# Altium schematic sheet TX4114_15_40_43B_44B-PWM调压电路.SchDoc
size A4
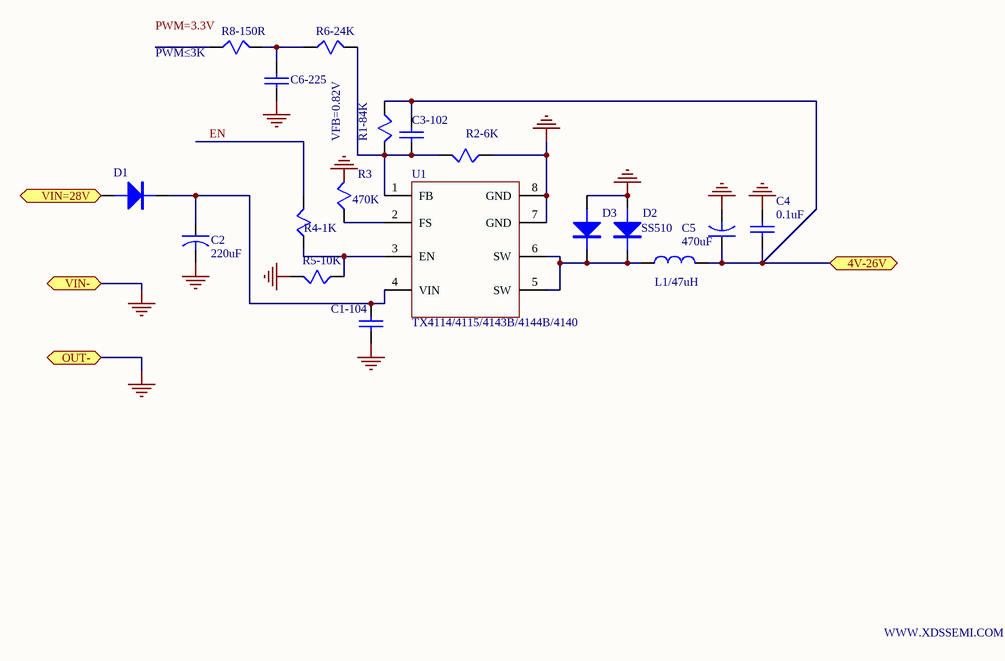
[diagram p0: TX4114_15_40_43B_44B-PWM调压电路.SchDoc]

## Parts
C1-104  (no value)  [0805R]
C2  220uF  [c8*12]
C3-102  (no value)  [0805R]
C4  0.1uF  [1206R]
C5  470uF  [C8*12]
C6-225  (no value)  [0805R]
D1  DIODE  [SMB]  (value not drawn)
D2  SS510  [SMB]
D3  (no value)  [SMB]
L1/47uH  (no value)  [CDRH127]
R1-84K  (no value)  [0805R]
R2-6K  (no value)  [0805R]
R3  470K  [0805R]
R4-1K  (no value)  [0805R]
R5-10K  (no value)  [0805R]
R6-24K  (no value)  [0805R]
R8-150R  (no value)  [0805R]
U1  TX4114/4115/4143B/4144B/4140

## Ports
4V-26V, OUT-, VIN-, VIN=28V

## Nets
GND: C1-104.2 C2.2 C4.1 C5.2 C6-225.1 D2.1(A) D3.1(A) R2-6K.1 R3.2 R5-10K.2 U1.7(GND) U1.8(GND) ; port VIN-, port OUT-
4V-26V: C3-102.2 C4.2 C5.1 L1/47uH.2 R1-84K.1 ; port 4V-26V
EN: R4-1K.2
VIN=28V: D1.1(A) ; port VIN=28V
NetC1-104_1: C1-104.1 C2.1 D1.2(K) U1.4(VIN)
NetC3-102_1: C3-102.1 R1-84K.2 R2-6K.2 R6-24K.2 U1.1(FB)
NetC6-225_2: C6-225.2 R6-24K.1 R8-150R.2
NetD2_2: D2.2(K) D3.2(K) L1/47uH.1 U1.5(SW) U1.6(SW)
NetR3_1: R3.1 U1.2(FS)
NetR4-1K_1: R4-1K.1 R5-10K.1 U1.3(EN)

Not connected (* = marked no-connect by the designer): R8-150R 1

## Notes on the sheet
- (near R8-150R) PWM≤3K
- VFB=0.82V
- WWW.XDSSEMI.COM
- Labels drawn without touching a wire or pin: PWM=3.3V

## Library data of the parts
C1-104 C3-102 C4 C6-225 = CAP: Capacitor
C2 C5 = CAPACITOR
D2 D3 = DIODE
L1/47uH = INDUCTOR
R1-84K R2-6K R3 R4-1K R5-10K R6-24K R8-150R = RES1_1
U1 = TX41XX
